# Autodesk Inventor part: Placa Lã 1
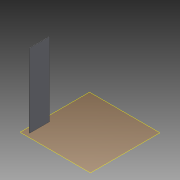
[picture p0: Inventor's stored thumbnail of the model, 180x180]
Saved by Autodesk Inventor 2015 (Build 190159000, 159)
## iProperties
Created: 2015-04
Part Number: Placa Lã 1
Material: Generic
Document SubType Name: Modeling
Designer: suporte
Density: 1 g/cm^3
Appearance: Default
Author: suporte
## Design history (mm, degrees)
workplane "Work Plane1"
sketch "Sketch1"
  geometry: L1 (-856.25, -313.1)-(-843.75, -313.1); L2 (-843.75, -313.1)-(-843.75, -875); L3 (-843.75, -875)-(-856.25, -875); L4 (-856.25, -875)-(-856.25, -313.1); L5 (-840.466, -875)-(-859.534, -875) reference; L6 (-840.466, -313.1)-(-859.534, -313.1) reference; 3 further points
  constraints: 8 end point, 4 midpoint, 2 parallel, 1 horizontal, 1 perpendicular
  dimensions: "d0" = 12.5 distance of L2.end L3.end
extrude "Extrusion1" new body sketch "Sketch1" distance "d1" = 2100; taper "d2" = 0 deg
body "Solid1"
node "Reference1"
node "Reference2"
